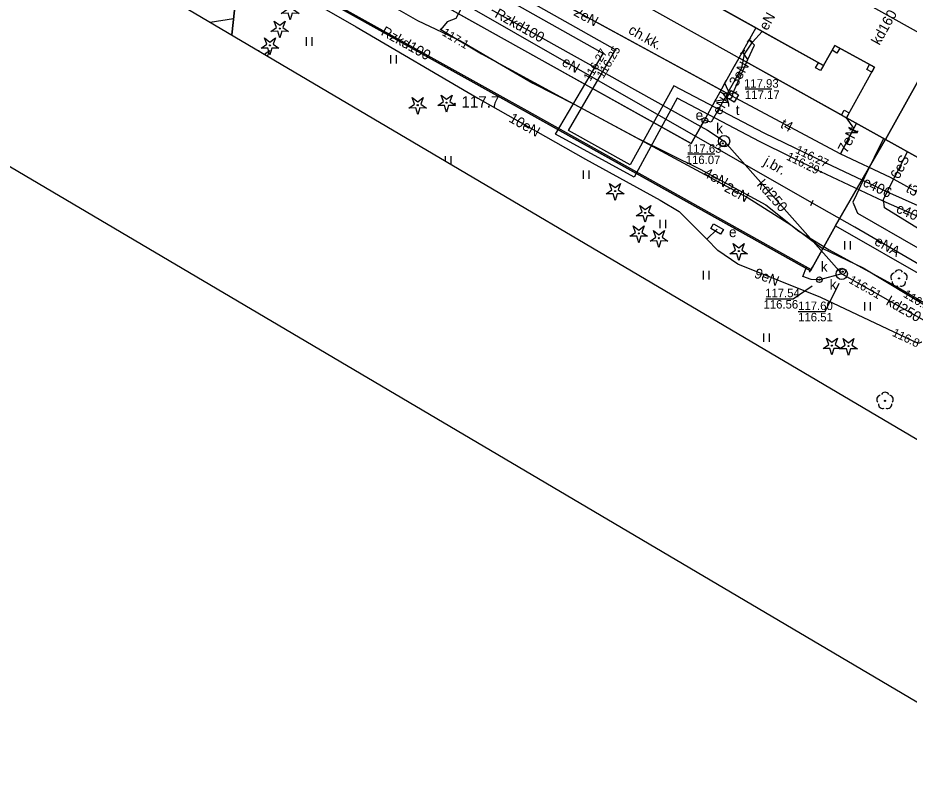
# Model space of a CAD drawing. Extents: x 6434771 to 6436222, y 5663454 to 5664782.
# Drawn here: x 6435277.1 to 6435356, y 5663705.5 to 5663773 of the extents above; entities that cross this region are included whole.
import ezdxf

# ---------------------------------------------------------------- set-up
doc = ezdxf.new("R2010")
doc.units = 0
for name, color, linetype in [('Warstwa 1', 7, 'Continuous'), ('Warstwa 10', 7, 'Continuous'), ('Warstwa 11', 7, 'Continuous'), ('Warstwa 12', 7, 'Continuous'), ('Warstwa 13', 7, 'Continuous'), ('Warstwa 14', 7, 'Continuous'), ('Warstwa 15', 7, 'Continuous'), ('Warstwa 2', 7, 'Continuous'), ('Warstwa 20', 7, 'Continuous'), ('Warstwa 21', 7, 'Continuous'), ('Warstwa 3', 7, 'Continuous'), ('Warstwa 33', 7, 'Continuous'), ('Warstwa 4', 7, 'Continuous'), ('Warstwa 5', 7, 'Continuous'), ('Warstwa 6', 7, 'Continuous'), ('Warstwa 63', 7, 'Continuous'), ('Warstwa 7', 7, 'Continuous'), ('Warstwa 8', 7, 'Continuous'), ('Warstwa 9', 7, 'Continuous')]:
    doc.layers.add(name, color=color, linetype=linetype)

msp = doc.modelspace()

# ---------------------------------------------------------------- linework, layer by layer
at = {"layer": 'Warstwa 1'}
for points in [[(6435358.6, 5663770.75), (6435353.88, 5663762.28), (6435350.43, 5663764.21), (6435352.9, 5663768.67), (6435349.4, 5663770.61), (6435348.38, 5663768.83), (6435316.59, 5663786.57), (6435315.32, 5663794.07), (6435315.68, 5663794.72)], [(6435363.18, 5663757.5), (6435364.23, 5663756.91), (6435364.06, 5663756.63), (6435353.88, 5663762.28), (6435358.6, 5663770.75), (6435367.72, 5663765.63)]]:
    msp.add_lwpolyline(points, close=True, dxfattribs=at)
at = {"layer": 'Warstwa 10'}
for points in [[(6435277.98, 5663796.72), (6435309.53, 5663779.08), (6435337.54, 5663763.44)], [(6435275.71, 5663790.757), (6435281.75, 5663787.39), (6435302.25, 5663775.95), (6435321.89, 5663764.99), (6435346.24, 5663751.37), (6435347.29, 5663750.78)], [(6435298.409, 5663770.139), (6435298.403, 5663770.157), (6435298.486, 5663770.094)], [(6435298.939, 5663769.826), (6435299.373, 5663770.157), (6435299.203, 5663769.671)], [(6435361.782, 5663732.745), (6435362.64, 5663734.21), (6435365.95, 5663739.66), (6435367.84, 5663744.26), (6435367.54, 5663745.85), (6435365.9, 5663747.91), (6435362.42, 5663750.92), (6435353.78, 5663756.25), (6435353.7, 5663757.02), (6435355.817, 5663761.205)]]:
    msp.add_lwpolyline(points, dxfattribs=at)
for points in [[(6435300.425, 5663773.435), (6435300.927, 5663773.782), (6435300.725, 5663774.358), (6435301.21, 5663773.988), (6435301.695, 5663774.358), (6435301.493, 5663773.782), (6435301.995, 5663773.435), (6435301.385, 5663773.449), (6435301.21, 5663772.865), (6435301.035, 5663773.449)], [(6435299.502, 5663771.841), (6435300.004, 5663772.188), (6435299.802, 5663772.764), (6435300.287, 5663772.394), (6435300.772, 5663772.764), (6435300.57, 5663772.188), (6435301.072, 5663771.841), (6435300.462, 5663771.855), (6435300.287, 5663771.271), (6435300.112, 5663771.855)], [(6435298.633, 5663770.356), (6435299.135, 5663770.703), (6435298.933, 5663771.279), (6435299.418, 5663770.909), (6435299.903, 5663771.279), (6435299.701, 5663770.703), (6435300.203, 5663770.356), (6435299.593, 5663770.37), (6435299.418, 5663769.786), (6435299.243, 5663770.37)], [(6435311.709, 5663765.065), (6435312.211, 5663765.412), (6435312.009, 5663765.988), (6435312.494, 5663765.618), (6435312.979, 5663765.988), (6435312.777, 5663765.412), (6435313.279, 5663765.065), (6435312.669, 5663765.079), (6435312.494, 5663764.495), (6435312.319, 5663765.079)], [(6435314.262, 5663765.287), (6435314.764, 5663765.634), (6435314.562, 5663766.21), (6435315.047, 5663765.84), (6435315.532, 5663766.21), (6435315.33, 5663765.634), (6435315.832, 5663765.287), (6435315.222, 5663765.301), (6435315.047, 5663764.717), (6435314.872, 5663765.301)], [(6435329.175, 5663757.475), (6435329.677, 5663757.822), (6435329.475, 5663758.398), (6435329.96, 5663758.028), (6435330.445, 5663758.398), (6435330.243, 5663757.822), (6435330.745, 5663757.475), (6435330.135, 5663757.489), (6435329.96, 5663756.905), (6435329.785, 5663757.489)], [(6435331.835, 5663755.535), (6435332.337, 5663755.882), (6435332.135, 5663756.458), (6435332.62, 5663756.088), (6435333.105, 5663756.458), (6435332.903, 5663755.882), (6435333.405, 5663755.535), (6435332.795, 5663755.549), (6435332.62, 5663754.965), (6435332.445, 5663755.549)], [(6435331.265, 5663753.725), (6435331.767, 5663754.072), (6435331.565, 5663754.648), (6435332.05, 5663754.278), (6435332.535, 5663754.648), (6435332.333, 5663754.072), (6435332.835, 5663753.725), (6435332.225, 5663753.739), (6435332.05, 5663753.155), (6435331.875, 5663753.739)], [(6435333.045, 5663753.305), (6435333.547, 5663753.652), (6435333.345, 5663754.228), (6435333.83, 5663753.858), (6435334.315, 5663754.228), (6435334.113, 5663753.652), (6435334.615, 5663753.305), (6435334.005, 5663753.319), (6435333.83, 5663752.735), (6435333.655, 5663753.319)], [(6435340.115, 5663752.165), (6435340.617, 5663752.512), (6435340.415, 5663753.088), (6435340.9, 5663752.718), (6435341.385, 5663753.088), (6435341.183, 5663752.512), (6435341.685, 5663752.165), (6435341.075, 5663752.179), (6435340.9, 5663751.595), (6435340.725, 5663752.179)], [(6435348.353, 5663743.801), (6435348.855, 5663744.148), (6435348.653, 5663744.724), (6435349.138, 5663744.354), (6435349.623, 5663744.724), (6435349.421, 5663744.148), (6435349.923, 5663743.801), (6435349.313, 5663743.815), (6435349.138, 5663743.231), (6435348.963, 5663743.815)], [(6435349.823, 5663743.76), (6435350.325, 5663744.107), (6435350.123, 5663744.683), (6435350.608, 5663744.313), (6435351.093, 5663744.683), (6435350.891, 5663744.107), (6435351.393, 5663743.76), (6435350.783, 5663743.774), (6435350.608, 5663743.19), (6435350.433, 5663743.774)]]:
    msp.add_lwpolyline(points, close=True, dxfattribs=at)
for centre in [(6435300.287, 5663772.096), (6435299.418, 5663770.611), (6435312.494, 5663765.32), (6435315.047, 5663765.542), (6435329.96, 5663757.73), (6435332.62, 5663755.79), (6435332.05, 5663753.98), (6435333.83, 5663753.56), (6435340.9, 5663752.42), (6435349.138, 5663744.056), (6435350.608, 5663744.015)]:
    msp.add_circle(centre, 0.05, dxfattribs=at)
at = {"layer": 'Warstwa 11'}
for centre in [(6435355.07, 5663750), (6435353.84, 5663739.18)]:
    msp.add_circle(centre, 0.05, dxfattribs=at)
for centre, start, end in [((6435354.713, 5663750.116), 102.14713, 221.85287), ((6435355.07, 5663750.375), 30.14713, 149.85287), ((6435355.427, 5663750.116), 318.14713, 77.85287), ((6435354.85, 5663749.697), 174.14713, 293.85287), ((6435355.29, 5663749.697), 246.14713, 5.85287), ((6435353.84, 5663739.555), 30.14713, 149.85287), ((6435353.483, 5663739.296), 102.14713, 221.85287), ((6435354.197, 5663739.296), 318.14713, 77.85287), ((6435353.62, 5663738.877), 174.14713, 293.85287), ((6435354.06, 5663738.877), 246.14713, 5.85287)]:
    msp.add_arc(centre, 0.375, start, end, dxfattribs=at)
at = {"layer": 'Warstwa 12'}
for points in [[(6435282.531, 5663791.508), (6435283.67, 5663790.604), (6435285.19, 5663788.156), (6435286.31, 5663787.332), (6435300.337, 5663778.662), (6435301.931, 5663778.183), (6435304.562, 5663777.371), (6435306.488, 5663776.248), (6435312.477, 5663772.805), (6435316.286, 5663770.999), (6435322.692, 5663767.272), (6435326.389, 5663765.387), (6435341.741, 5663757.141), (6435345.492, 5663754.736), (6435348.278, 5663752.682), (6435351.917, 5663750.948), (6435357.914, 5663747.315), (6435358.315, 5663747.4), (6435361.645, 5663754.021), (6435363.322, 5663757.04)], [(6435427.17, 5663739.193), (6435426.34, 5663739.17), (6435421.79, 5663741.74), (6435415.76, 5663730.22), (6435403.78, 5663736.47), (6435393.01, 5663741.8), (6435387.55, 5663744.3), (6435376.19, 5663748.47), (6435370.47, 5663750.27), (6435364.67, 5663752.32), (6435359.09, 5663754.45), (6435353.66, 5663756.84), (6435348.17, 5663759.42), (6435342.78, 5663762.07), (6435335.44, 5663765.94), (6435331.63, 5663758.95), (6435324.69, 5663762.75), (6435328.9, 5663769.89), (6435296.25, 5663788.25), (6435294.655, 5663789.682)], [(6435427.17, 5663739.193), (6435426.57, 5663739.84), (6435421.37, 5663742.74), (6435415.39, 5663731.39), (6435403.97, 5663737.3), (6435393.25, 5663742.68), (6435387.83, 5663745.16), (6435382.26, 5663747.43), (6435376.45, 5663749.28), (6435370.72, 5663751.07), (6435365.02, 5663753.03), (6435359.55, 5663755.18), (6435354, 5663757.65), (6435348.62, 5663760.2), (6435343.16, 5663762.85), (6435335.14, 5663767.04), (6435331.28, 5663760.06), (6435325.83, 5663763.09), (6435330, 5663770.22), (6435296.67, 5663789), (6435294.655, 5663789.682)], [(6435315.97, 5663779.49), (6435316.16, 5663779.36), (6435316.72, 5663778.99), (6435340.13, 5663766.23), (6435340.35, 5663766.11)], [(6435318.17, 5663778.21), (6435339.91, 5663766.35)], [(6435297.86, 5663777.23), (6435302.56, 5663774.83), (6435307.05, 5663772.26), (6435317.8, 5663765.94), (6435327.35, 5663760.54), (6435333.93, 5663756.93), (6435335.62, 5663755.91), (6435338.07, 5663753.46)], [(6435315.85, 5663775.49), (6435315.9, 5663775), (6435316.6, 5663774.38), (6435315.88, 5663772.99), (6435315.09, 5663772.68), (6435314.53, 5663772.02), (6435318.14, 5663769.85), (6435325.12, 5663766.05), (6435331.93, 5663762.4), (6435337.49, 5663759.67), (6435343.3, 5663756.5), (6435346.21, 5663754.18), (6435348.91, 5663752.54), (6435354.99, 5663749.19), (6435360.95, 5663745.72), (6435362.98, 5663745.33)], [(6435347.37, 5663756.69), (6435314.624, 5663775.443)], [(6435342.11, 5663770.9), (6435342.969, 5663771.849)], [(6435341.41, 5663769.83), (6435342.11, 5663770.9)], [(6435341.7, 5663769.35), (6435342.28, 5663770.63), (6435341.82, 5663771.08)], [(6435342.11, 5663770.9), (6435341.82, 5663771.08)], [(6435339.91, 5663766.35), (6435341.17, 5663768.62), (6435341.41, 5663769.83)], [(6435341.7, 5663769.35), (6435341.23, 5663770.04)], [(6435341.41, 5663769.83), (6435341.23, 5663770.04)], [(6435340.35, 5663766.11), (6435340.37, 5663766.36), (6435341.7, 5663769.35)], [(6435340.35, 5663766.11), (6435340.13, 5663766.23), (6435339.68, 5663767.27)], [(6435339.91, 5663766.35), (6435338.46, 5663763.83), (6435337.9, 5663763.98)], [(6435340.35, 5663766.11), (6435340.17, 5663765.92), (6435338.77, 5663765.65)], [(6435340.35, 5663766.11), (6435340.56, 5663765.99), (6435349.89, 5663761.03)], [(6435349.89, 5663761.03), (6435351.08, 5663763.28), (6435350.43, 5663764.21)], [(6435351.309, 5663763.718), (6435351.08, 5663763.28), (6435349.89, 5663761.03), (6435354.28, 5663758.95), (6435363.01, 5663754.14), (6435366.48, 5663754.58)], [(6435353.692, 5663762.385), (6435352.02, 5663758.95), (6435351.3, 5663757.42), (6435350.98, 5663756.73), (6435351.39, 5663755.78), (6435362.08, 5663749.65), (6435365.72, 5663747.52), (6435366.48, 5663746.82), (6435369.91, 5663744.72)], [(6435349.89, 5663761.03), (6435354.28, 5663758.95), (6435363.01, 5663754.14), (6435363.74, 5663753.9), (6435363.96, 5663753.76), (6435364.07, 5663753.99), (6435366.48, 5663754.58), (6435367.69, 5663753.89)], [(6435362.385, 5663732.389), (6435362.687, 5663732.874), (6435366.615, 5663740.077), (6435367.171, 5663741.158), (6435367.363, 5663742.09), (6435367.428, 5663743.013), (6435366.73, 5663745.215), (6435366.555, 5663745.67), (6435362.782, 5663747.85), (6435357.858, 5663750.64), (6435351.154, 5663754.539), (6435347.37, 5663756.69)], [(6435338.07, 5663753.46), (6435338.98, 5663754.37)], [(6435362.98, 5663745.33), (6435361.9, 5663745.07), (6435360.25, 5663745.62), (6435356.76, 5663744.25), (6435348.16, 5663748.32), (6435340.81, 5663751.25), (6435339.05, 5663752.47), (6435338.07, 5663753.46)]]:
    msp.add_lwpolyline(points, dxfattribs=at)
at = {"layer": 'Warstwa 13'}
msp.add_circle((6435315.782, 5663765.453), 0.045, dxfattribs=at)
at = {"layer": 'Warstwa 14'}
for p, q in [((6435343.829, 5663766.75), (6435341.46, 5663766.75)), ((6435338.77, 5663760.993), (6435336.401, 5663760.993))]:
    msp.add_line(p, q, dxfattribs=at)
for points in [[(6435343.28, 5663748.209), (6435345.72, 5663748.209), (6435347.386, 5663749.339)], [(6435346.15, 5663747.079), (6435348.54, 5663747.079), (6435349.769, 5663749.584)]]:
    msp.add_lwpolyline(points, dxfattribs=at)
for centre in [(6435314.53, 5663772.02), (6435328.9, 5663769.89), (6435330, 5663770.22), (6435340.35, 5663766.11), (6435339.5, 5663761.94), (6435348.62, 5663760.2), (6435348.17, 5663759.42), (6435350.09, 5663750.6), (6435350.09, 5663750.6), (6435348.03, 5663749.89)]:
    msp.add_circle(centre, 0.045, dxfattribs=at)
at = {"layer": 'Warstwa 15'}
for centre in [(6435339.6, 5663762.14), (6435350.01, 5663750.4)]:
    msp.add_circle(centre, 0.5, dxfattribs=at)
at = {"layer": 'Warstwa 2'}
for points in [[(6435338.01, 5663764.27), (6435336.69, 5663761.93), (6435309.59, 5663777.07), (6435277.13, 5663795.19), (6435278.38, 5663797.42)], [(6435342.42, 5663772.16), (6435340.5, 5663768.74)]]:
    msp.add_lwpolyline(points, dxfattribs=at)
at = {"layer": 'Warstwa 20'}
for p, q in [((6435341.66, 5663770.888), (6435341.98, 5663771.272)), ((6435341.037, 5663769.881), (6435341.423, 5663770.199)), ((6435341.065, 5663769.852), (6435341.395, 5663770.228)), ((6435339.562, 5663767.049), (6435339.798, 5663767.491)), ((6435338.656, 5663765.427), (6435338.884, 5663765.873)), ((6435337.421, 5663763.22), (6435337.659, 5663763.66)), ((6435347.27, 5663756.461), (6435347.47, 5663756.919)), ((6435347.17, 5663750.561), (6435347.41, 5663750.999))]:
    msp.add_line(p, q, dxfattribs=at)
at = {"layer": 'Warstwa 21'}
for points in [[(6435293.682, 5663779.864), (6435296.405, 5663774.85), (6435296.042, 5663771.535)], [(6435339.288, 5663753.904), (6435338.422, 5663754.403), (6435338.672, 5663754.836), (6435339.538, 5663754.337), (6435339.288, 5663753.904)]]:
    msp.add_lwpolyline(points, dxfattribs=at)
at = {"layer": 'Warstwa 3'}
msp.add_lwpolyline([(6435338.01, 5663764.27), (6435340.5, 5663768.74)], dxfattribs=at)
for centre, start, end in [((6435339.985, 5663767.815), 240.88292, 300.88292), ((6435338.525, 5663765.195), 0.88292, 60.88292)]:
    msp.add_arc(centre, 1.5, start, end, dxfattribs=at)
at = {"layer": 'Warstwa 33'}
for p, q in [((6435310.93, 5663786.27), (6435350.43, 5663764.21)), ((6435316.59, 5663786.57), (6435348.38, 5663768.83)), ((6435348.38, 5663768.83), (6435349.4, 5663770.61)), ((6435349.4, 5663770.61), (6435352.9, 5663768.67)), ((6435350.43, 5663764.21), (6435352.9, 5663768.67))]:
    msp.add_line(p, q, dxfattribs=at)
for points in [[(6435349.834, 5663770.362), (6435349.586, 5663769.928), (6435349.152, 5663770.176), (6435349.4, 5663770.61)], [(6435348.136, 5663768.394), (6435347.7, 5663768.638), (6435347.944, 5663769.074), (6435348.38, 5663768.83)], [(6435352.657, 5663768.233), (6435352.22, 5663768.476), (6435352.463, 5663768.913), (6435352.9, 5663768.67)], [(6435349.992, 5663764.452), (6435350.234, 5663764.89), (6435350.672, 5663764.648), (6435350.43, 5663764.21)]]:
    msp.add_lwpolyline(points, close=True, dxfattribs=at)
at = {"layer": 'Warstwa 4'}
msp.add_lwpolyline([(6435339.838, 5663765.972), (6435340.212, 5663766.622), (6435340.862, 5663766.248), (6435340.488, 5663765.598)], close=True, dxfattribs=at)
for centre in [(6435337.9, 5663763.98), (6435339.5, 5663761.94), (6435350.09, 5663750.6), (6435348.03, 5663749.89)]:
    msp.add_circle(centre, 0.25, dxfattribs=at)
at = {"layer": 'Warstwa 5'}
for p, q in [((6435302.12, 5663775.87), (6435321.83, 5663764.87)), ((6435296.042, 5663771.535), (6435296.405, 5663774.85)), ((6435302.653, 5663770.584), (6435302.653, 5663771.334)), ((6435303.153, 5663770.584), (6435303.153, 5663771.334)), ((6435310.123, 5663768.998), (6435310.123, 5663769.748)), ((6435310.623, 5663768.998), (6435310.623, 5663769.748)), ((6435321.83, 5663764.87), (6435347.23, 5663750.67)), ((6435314.952, 5663760.377), (6435314.952, 5663760.809)), ((6435315.452, 5663760.082), (6435315.452, 5663760.809)), ((6435327.158, 5663758.807), (6435327.158, 5663759.557)), ((6435327.658, 5663758.807), (6435327.658, 5663759.557)), ((6435333.95, 5663754.445), (6435333.95, 5663755.195)), ((6435334.45, 5663754.445), (6435334.45, 5663755.195)), ((6435347.23, 5663750.67), (6435349.46, 5663754.66)), ((6435349.46, 5663754.66), (6435361.89, 5663747.52)), ((6435350.286, 5663752.557), (6435350.286, 5663753.307)), ((6435350.786, 5663752.557), (6435350.786, 5663753.307)), ((6435337.778, 5663749.912), (6435337.778, 5663750.662)), ((6435338.278, 5663749.912), (6435338.278, 5663750.662)), ((6435352.046, 5663747.158), (6435352.046, 5663747.908)), ((6435352.546, 5663747.158), (6435352.546, 5663747.908)), ((6435343.108, 5663744.383), (6435343.108, 5663745.133)), ((6435343.608, 5663744.383), (6435343.608, 5663745.133))]:
    msp.add_line(p, q, dxfattribs=at)
at = {"layer": 'Warstwa 6'}
msp.add_lwpolyline([(6435349.46, 5663754.66), (6435347.23, 5663750.67), (6435321.83, 5663764.87), (6435302.12, 5663775.87), (6435281.67, 5663787.27), (6435275.708, 5663790.592)], dxfattribs=at)
for centre in [(6435340.35, 5663766.11), (6435339.5, 5663761.94), (6435350.09, 5663750.6), (6435348.03, 5663749.89)]:
    msp.add_circle(centre, 0.045, dxfattribs=at)
at = {"layer": 'Warstwa 63'}
for points in [[(6434770.578, 5664058.35), (6435197.816, 5664782.406), (6436221.837, 5664178.169), (6435794.599, 5663454.114)], [(6435677.2, 5663546.629), (6436084.093, 5664236.205), (6435222.122, 5664744.822), (6434815.229, 5664055.245)]]:
    msp.add_lwpolyline(points, close=True, dxfattribs=at)
at = {"layer": 'Warstwa 7'}
for points in [[(6435337.54, 5663763.44), (6435338.14, 5663763.1), (6435339.6, 5663762.14)], [(6435339.6, 5663762.14), (6435350.01, 5663750.4)], [(6435350.01, 5663750.4), (6435348.03, 5663749.89), (6435347.31, 5663749.91), (6435346.57, 5663750.18), (6435346.884, 5663751.008)], [(6435350.01, 5663750.4), (6435364.94, 5663741.98), (6435377.36, 5663741.1), (6435377.78, 5663740.99)]]:
    msp.add_lwpolyline(points, dxfattribs=at)
at = {"layer": 'Warstwa 8'}
for p, q in [((6435309.59, 5663777.07), (6435336.69, 5663761.93)), ((6435302.12, 5663775.87), (6435321.83, 5663764.87)), ((6435340.5, 5663768.74), (6435340.934, 5663769.513)), ((6435340.934, 5663769.513), (6435349.993, 5663764.454)), ((6435338.01, 5663764.27), (6435340.5, 5663768.74)), ((6435321.83, 5663764.87), (6435347.23, 5663750.67)), ((6435336.69, 5663761.93), (6435338.01, 5663764.27)), ((6435349.993, 5663764.454), (6435350.43, 5663764.21)), ((6435350.43, 5663764.21), (6435353.88, 5663762.28)), ((6435349.46, 5663754.66), (6435353.88, 5663762.28)), ((6435349.46, 5663754.66), (6435353.88, 5663762.28)), ((6435353.88, 5663762.28), (6435364.06, 5663756.63)), ((6435347.23, 5663750.67), (6435349.46, 5663754.66)), ((6435349.46, 5663754.66), (6435361.89, 5663747.52))]:
    msp.add_line(p, q, dxfattribs=at)
at = {"layer": 'Warstwa 9'}
for p, q in [((6435316.59, 5663786.57), (6435348.38, 5663768.83)), ((6435309.59, 5663777.07), (6435336.69, 5663761.93)), ((6435294.138, 5663772.659), (6435296.201, 5663772.985)), ((6435348.38, 5663768.83), (6435349.4, 5663770.61)), ((6435349.4, 5663770.61), (6435352.9, 5663768.67)), ((6435340.5, 5663768.74), (6435340.934, 5663769.513)), ((6435340.934, 5663769.513), (6435350.43, 5663764.21)), ((6435338.01, 5663764.27), (6435340.5, 5663768.74)), ((6435350.43, 5663764.21), (6435352.9, 5663768.67)), ((6435336.69, 5663761.93), (6435338.01, 5663764.27))]:
    msp.add_line(p, q, dxfattribs=at)
msp.add_lwpolyline([(6435296.042, 5663771.535), (6435296.405, 5663774.85), (6435293.682, 5663779.864), (6435290.973, 5663775.068), (6435291.602, 5663774.712), (6435292.146, 5663774.009), (6435292.216, 5663773.793)], dxfattribs=at)

# ---------------------------------------------------------------- texts
at = {"layer": 'Warstwa 11'}
for s, rotation, p in [('Rzkd100', 330.8201, (6435319.234, 5663773.146)), ('Rzkd100', 330.83729, (6435309.172, 5663771.571)), ('6eS', 63.1686, (6435355.059, 5663758.709))]:
    msp.add_text(s, height=0.9, rotation=rotation, dxfattribs=at).set_placement(p)
at = {"layer": 'Warstwa 13'}
for s, height, rotation, p in [('2eN', 0.9, 331.38733, (6435326.217, 5663773.308)), ('eN', 0.9, 60.83666, (6435343.419, 5663771.855)), ('eN', 0.9, 330.20131, (6435325.165, 5663768.888)), ('3eN', 0.9025, 60.96844, (6435340.767, 5663766.913)), ('eN', 0.9025, 60.08608, (6435339.287, 5663764.374)), ('10eN', 0.9, 330.51643, (6435320.484, 5663763.905)), ('t4', 0.9, 332.00612, (6435344.503, 5663763.384)), ('7eN', 0.95, 62.12581, (6435350.437, 5663761.004)), ('t', 0.95, 62.12581, (6435351.324, 5663762.748)), ('4eN', 0.9, 331.3816, (6435337.692, 5663759.069)), ('c406', 0.9, 334.64173, (6435351.802, 5663758.21)), ('2eN', 0.9, 331.75975, (6435339.546, 5663757.75)), ('t3', 0.9, 331.14669, (6435355.614, 5663757.705)), ('c406', 0.9, 336.24601, (6435354.749, 5663755.869)), ('eNA', 0.9, 330.5107, (6435352.816, 5663753.04)), ('9eN', 0.9, 338.26855, (6435342.189, 5663750.115))]:
    msp.add_text(s, height=height, rotation=rotation, dxfattribs=at).set_placement(p)
msp.add_text('117.7', height=1, dxfattribs=at).set_placement((6435316.367, 5663765.116))
at = {"layer": 'Warstwa 14'}
for s, rotation, p in [('117.1', 328.99237, (6435314.585, 5663771.55)), ('116.25', 59.67928, (6435328.914, 5663767.62)), ('116.27', 59.47302, (6435327.755, 5663767.388)), ('116.29', 333.81667, (6435345.051, 5663760.535)), ('116.27', 334.10888, (6435345.848, 5663761.128)), ('116.51', 330.57946, (6435350.568, 5663749.655)), ('116.83', 328.79183, (6435355.394, 5663748.414)), ('116.8', 334.67611, (6435354.408, 5663744.948))]:
    msp.add_text(s, height=0.75, rotation=rotation, dxfattribs=at).set_placement(p)
for s, p in [('117.17', (6435341.445, 5663765.871)), ('116.07', (6435336.203, 5663760.114)), ('116.56', (6435343.087, 5663747.334)), ('116.51', (6435346.151, 5663746.204))]:
    msp.add_text(s, height=0.75, dxfattribs=at).set_placement(p)
at = {"layer": 'Warstwa 21'}
msp.add_text('e', height=0.9, dxfattribs=at).set_placement((6435340.03, 5663753.653))
at = {"layer": 'Warstwa 5'}
for s, p in [('t', (6435340.632, 5663764.447)), ('e', (6435337.078, 5663763.997)), ('k', (6435338.901, 5663762.815)), ('k', (6435348.155, 5663750.594)), ('k', (6435348.945, 5663749.015))]:
    msp.add_text(s, height=0.9, dxfattribs=at).set_placement(p)
at = {"layer": 'Warstwa 6'}
for s, p in [('117.93', (6435341.36, 5663766.871)), ('117.63', (6435336.301, 5663761.114)), ('117.54', (6435343.23, 5663748.334)), ('117.60', (6435346.15, 5663747.204))]:
    msp.add_text(s, height=0.75, dxfattribs=at).set_placement(p)
at = {"layer": 'Warstwa 7'}
for s, rotation, p in [('kd160', 60.81947, (6435353.341, 5663770.565)), ('kd250', 311.56299, (6435342.446, 5663758.252)), ('kd250', 330.57946, (6435353.858, 5663747.713))]:
    msp.add_text(s, height=0.9, rotation=rotation, dxfattribs=at).set_placement(p)
at = {"layer": 'Warstwa 8'}
msp.add_text('j.br.', height=0.9, rotation=330.8201, dxfattribs=at).set_placement((6435343.017, 5663760.086))
at = {"layer": 'Warstwa 9'}
msp.add_text('ch.kk.', height=0.9, rotation=330.60238, dxfattribs=at).set_placement((6435331.052, 5663771.716))

doc.saveas('drawing.dxf')
